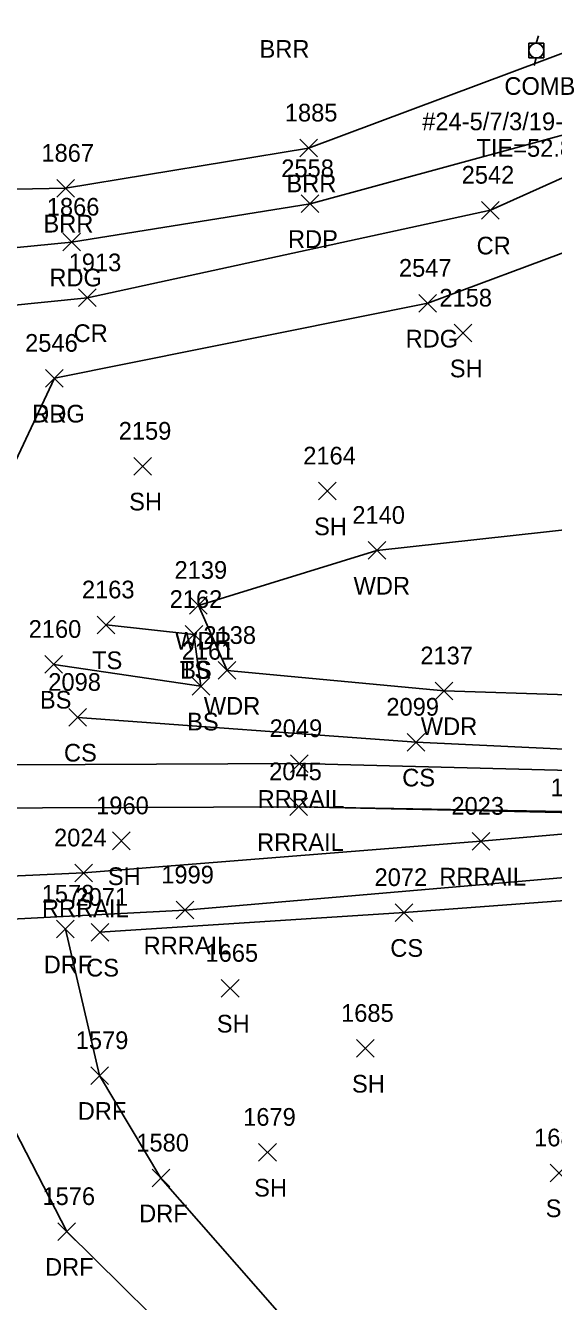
# Model space of a CAD drawing. Extents: x 1609623 to 1616187, y 756677 to 762826.
# Drawn here: x 1610243.7 to 1610303.4, y 761777.7 to 761921.9 of the extents above; entities that cross this region are included whole.
import ezdxf

# ---------------------------------------------------------------- set-up
doc = ezdxf.new("R2010")
doc.units = 0
for name, color, linetype in [('L_A', 7, 'Continuous'), ('L_I', 7, 'Continuous'), ('L_TIC', 7, 'Continuous'), ('LABL', 7, 'Continuous'), ('LAWA', 7, 'Continuous'), ('LELB', 7, 'Continuous'), ('P_A', 7, 'Continuous'), ('P_I', 7, 'Continuous'), ('P_TIC', 7, 'Continuous'), ('PET', 7, 'Continuous'), ('PEU', 7, 'Continuous'), ('PRC', 7, 'Continuous'), ('R_A', 7, 'Continuous'), ('R_I', 7, 'Continuous'), ('R_TIC', 7, 'Continuous'), ('RDF', 7, 'Continuous'), ('RDG', 7, 'Continuous'), ('RR', 7, 'Continuous'), ('U_A', 7, 'Continuous'), ('U_C', 7, 'Continuous'), ('UP', 7, 'Continuous')]:
    doc.layers.add(name, color=color, linetype=linetype)

msp = doc.modelspace()

# ---------------------------------------------------------------- linework, layer by layer
at = {"layer": 'L_TIC'}
for points in [[(1610274.72, 761907.1), (1610276.72, 761909.1)], [(1610276.72, 761907.1), (1610274.72, 761909.1)], [(1610247.25, 761902.55), (1610249.25, 761904.55)], [(1610249.25, 761902.55), (1610247.25, 761904.55)], [(1610292.19, 761886.18), (1610294.19, 761888.18)], [(1610294.19, 761886.18), (1610292.19, 761888.18)], [(1610255.95, 761871.13), (1610257.95, 761873.13)], [(1610257.95, 761871.13), (1610255.95, 761873.13)], [(1610276.85, 761868.33), (1610278.85, 761870.33)], [(1610278.85, 761868.33), (1610276.85, 761870.33)], [(1610282.44, 761861.62), (1610284.44, 761863.62)], [(1610284.44, 761861.62), (1610282.44, 761863.62)], [(1610262.26, 761855.4), (1610264.26, 761857.4)], [(1610264.26, 761855.4), (1610262.26, 761857.4)], [(1610251.83, 761853.19), (1610253.83, 761855.19)], [(1610253.83, 761853.19), (1610251.83, 761855.19)], [(1610261.75, 761852.11), (1610263.75, 761854.11)], [(1610263.75, 761852.11), (1610261.75, 761854.11)], [(1610261.75, 761852.11), (1610263.75, 761854.11)], [(1610263.75, 761852.11), (1610261.75, 761854.11)], [(1610245.9, 761848.73), (1610247.9, 761850.73)], [(1610247.9, 761848.73), (1610245.9, 761850.73)], [(1610265.51, 761848.04), (1610267.51, 761850.04)], [(1610267.51, 761848.04), (1610265.51, 761850.04)], [(1610262.54, 761846.26), (1610264.54, 761848.26)], [(1610264.54, 761846.26), (1610262.54, 761848.26)], [(1610290.04, 761845.73), (1610292.04, 761847.73)], [(1610292.04, 761845.73), (1610290.04, 761847.73)], [(1610248.62, 761842.74), (1610250.62, 761844.74)], [(1610250.62, 761842.74), (1610248.62, 761844.74)], [(1610286.86, 761839.93), (1610288.86, 761841.93)], [(1610288.86, 761839.93), (1610286.86, 761841.93)], [(1610253.53, 761828.78), (1610255.53, 761830.78)], [(1610255.53, 761828.78), (1610253.53, 761830.78)], [(1610285.51, 761820.67), (1610287.51, 761822.67)], [(1610287.51, 761820.67), (1610285.51, 761822.67)], [(1610251.13, 761818.44), (1610253.13, 761820.44)], [(1610253.13, 761818.44), (1610251.13, 761820.44)], [(1610265.85, 761812.11), (1610267.85, 761814.11)], [(1610267.85, 761812.11), (1610265.85, 761814.11)], [(1610281.13, 761805.32), (1610283.13, 761807.32)], [(1610283.13, 761805.32), (1610281.13, 761807.32)], [(1610270.07, 761793.57), (1610272.07, 761795.57)], [(1610272.07, 761793.57), (1610270.07, 761795.57)], [(1610303.03, 761791.24), (1610305.03, 761793.24)], [(1610305.03, 761791.24), (1610303.03, 761793.24)]]:
    msp.add_lwpolyline(points, dxfattribs=at)
at = {"layer": 'LABL'}
for points in [[(1610248.25, 761903.55), (1610212.86, 761902.85), (1610172.33, 761900.95), (1610131.44, 761903.3), (1610100.93, 761896.76), (1610074.3, 761892.77), (1610070.02, 761901.24), (1610088.05, 761924.14), (1610103.11, 761932.23), (1610130.22, 761924.96), (1610177.67, 761924.02), (1610222.12, 761925.25), (1610272.69, 761923.3), (1610298.02, 761931.54), (1610307.47, 761946.97), (1610343.23, 761952.19), (1610333.93, 761931.55), (1610306.47, 761919.59), (1610275.72, 761908.1)], [(1610275.72, 761908.1), (1610248.25, 761903.55)]]:
    msp.add_lwpolyline(points, dxfattribs=at)
at = {"layer": 'LAWA'}
msp.add_lwpolyline([(1610526.97, 761857.61), (1610496.05, 761855.92), (1610466.25, 761855.65), (1610453.5, 761854.66), (1610420.91, 761848.73), (1610387.01, 761845.92), (1610353.13, 761844.36), (1610319.01, 761845.83), (1610291.04, 761846.73), (1610266.51, 761849.04), (1610263.26, 761856.4), (1610283.44, 761862.62), (1610306.38, 761865.12), (1610332.85, 761874.22), (1610329.32, 761884.2), (1610350.34, 761886.85), (1610367.24, 761893.33), (1610366.39, 761903.57), (1610364.69, 761910.04), (1610391.22, 761924.07)], dxfattribs=at)
at = {"layer": 'LELB'}
for points in [[(1610249.62, 761843.74), (1610287.86, 761840.93), (1610324.56, 761839.21), (1610370.55, 761840.35), (1610409.04, 761843.86), (1610454.55, 761848.66), (1610503.04, 761852.15), (1610552.78, 761856.55), (1610588.39, 761859.94), (1610611.21, 761862.91), (1610623.76, 761863.72)], [(1610262.75, 761853.11), (1610252.83, 761854.19)], [(1610246.9, 761849.73), (1610263.54, 761847.26), (1610262.75, 761853.11)], [(1610252.13, 761819.44), (1610286.51, 761821.67), (1610318.33, 761824.07)]]:
    msp.add_lwpolyline(points, dxfattribs=at)
at = {"layer": 'P_TIC'}
for points in [[(1610274.89, 761900.81), (1610276.89, 761902.81)], [(1610276.89, 761900.81), (1610274.89, 761902.81)], [(1610295.28, 761900.07), (1610297.28, 761902.07)], [(1610297.28, 761900.07), (1610295.28, 761902.07)], [(1610247.92, 761896.46), (1610249.92, 761898.46)], [(1610249.92, 761896.46), (1610247.92, 761898.46)], [(1610249.72, 761890.17), (1610251.72, 761892.17)], [(1610251.72, 761890.17), (1610249.72, 761892.17)], [(1610288.19, 761889.55), (1610290.19, 761891.55)], [(1610290.19, 761889.55), (1610288.19, 761891.55)], [(1610245.98, 761881.07), (1610247.98, 761883.07)], [(1610247.98, 761881.07), (1610245.98, 761883.07)]]:
    msp.add_lwpolyline(points, dxfattribs=at)
at = {"layer": 'PET'}
for points in [[(1610414.5, 761964.62), (1610377.71, 761946.31), (1610343.21, 761928.18), (1610307.99, 761910.55), (1610275.89, 761901.81)], [(1610275.89, 761901.81), (1610248.92, 761897.46)]]:
    msp.add_lwpolyline(points, dxfattribs=at)
at = {"layer": 'PEU'}
for points in [[(1610246.98, 761882.07), (1610289.19, 761890.55), (1610323.19, 761903.21)], [(1610061.53, 761886.05), (1610095.83, 761889.43), (1610133.36, 761892.01), (1610173.59, 761893.05), (1610213.17, 761893.96), (1610248.92, 761897.46)]]:
    msp.add_lwpolyline(points, dxfattribs=at)
at = {"layer": 'PRC'}
for points in [[(1610478.04, 761990.3), (1610447.54, 761976.31), (1610423.7, 761963.3), (1610382.39, 761941.65), (1610345.03, 761922.97), (1610296.28, 761901.07)], [(1610296.28, 761901.07), (1610250.72, 761891.17)], [(1610012.87, 761874.99), (1610052.18, 761877.05), (1610092.88, 761880.29), (1610131.85, 761882.19), (1610172.93, 761884.85), (1610214.04, 761887.46), (1610250.72, 761891.17)]]:
    msp.add_lwpolyline(points, dxfattribs=at)
at = {"layer": 'R_TIC'}
for points in [[(1610245.98, 761881.07), (1610247.98, 761883.07)], [(1610247.98, 761881.07), (1610245.98, 761883.07)], [(1610273.66, 761837.51), (1610275.66, 761839.51)], [(1610275.66, 761837.51), (1610273.66, 761839.51)], [(1610273.6, 761832.63), (1610275.6, 761834.63)], [(1610275.6, 761832.63), (1610273.6, 761834.63)], [(1610273.6, 761832.63), (1610275.6, 761834.63)], [(1610275.6, 761832.63), (1610273.6, 761834.63)], [(1610294.2, 761828.73), (1610296.2, 761830.73)], [(1610296.2, 761828.73), (1610294.2, 761830.73)], [(1610249.28, 761825.15), (1610251.28, 761827.15)], [(1610251.28, 761825.15), (1610249.28, 761827.15)], [(1610260.76, 761820.96), (1610262.76, 761822.96)], [(1610262.76, 761820.96), (1610260.76, 761822.96)], [(1610247.23, 761818.8), (1610249.23, 761820.8)], [(1610249.23, 761818.8), (1610247.23, 761820.8)], [(1610251.09, 761802.24), (1610253.09, 761804.24)], [(1610253.09, 761802.24), (1610251.09, 761804.24)], [(1610258.02, 761790.66), (1610260.02, 761792.66)], [(1610260.02, 761790.66), (1610258.02, 761792.66)], [(1610247.38, 761784.61), (1610249.38, 761786.61)], [(1610249.38, 761784.61), (1610247.38, 761786.61)]]:
    msp.add_lwpolyline(points, dxfattribs=at)
at = {"layer": 'RDF'}
for points in [[(1610248.23, 761819.8), (1610252.09, 761803.24), (1610259.02, 761791.66), (1610278.62, 761769.29), (1610292.65, 761756.84)], [(1610264.31, 761756.11), (1610264.09, 761770.09), (1610248.38, 761785.61), (1610231.28, 761818.76)]]:
    msp.add_lwpolyline(points, dxfattribs=at)
at = {"layer": 'RDG'}
msp.add_lwpolyline([(1610239.97, 761839.19), (1610239.25, 761851.99), (1610240.2, 761867.74), (1610246.98, 761882.07)], dxfattribs=at)
at = {"layer": 'RR'}
for points in [[(1610920.34, 761877.5), (1610875.2, 761880.63), (1610823.88, 761880.35), (1610770.14, 761877.16), (1610718.25, 761872.56), (1610624.39, 761862.75), (1610528.95, 761852.85), (1610433.45, 761843.38), (1610390.08, 761839.1), (1610343.15, 761834.31), (1610326.86, 761832.49), (1610295.2, 761829.73), (1610250.28, 761826.15), (1610201.81, 761823.95), (1610155.3, 761823.62), (1610106.26, 761824.63), (1610057.65, 761827.02), (1610007.52, 761831.91), (1609961.32, 761837.48), (1609915.47, 761844.69), (1609871.57, 761853.1), (1609828.18, 761862.73), (1609811.27, 761866.9)], [(1610356.77, 761837.2), (1610311.16, 761837.59), (1610274.66, 761838.51), (1610226.22, 761838.28), (1610178.94, 761837.67), (1610131.97, 761838.32), (1610083.45, 761840.67), (1610036.86, 761844.06), (1609989.49, 761848.51), (1609944.78, 761853.81), (1609900.87, 761860.46), (1609856.95, 761868.77), (1609813.49, 761878.61)], [(1609812.23, 761861.59), (1609849.51, 761852.68), (1609889.11, 761844.53), (1609934.67, 761836.61), (1609980.82, 761829.97), (1610026.24, 761824.91), (1610071.82, 761821.22), (1610118.39, 761819.39), (1610165.38, 761818.61), (1610213.1, 761819.4), (1610261.76, 761821.96), (1610309.94, 761826.07), (1610356.6, 761830.72), (1610389.15, 761834), (1610434.7, 761838.51), (1610480.7, 761843.13), (1610575.97, 761852.51), (1610672.94, 761862.83), (1610719.08, 761867.65), (1610767.25, 761871.97), (1610815.87, 761875.05), (1610864.69, 761875.82), (1610894.81, 761874.78)], [(1609812.59, 761873.79), (1609856.08, 761863.93), (1609900.7, 761855.53), (1609944.64, 761848.95), (1609989.39, 761843.6), (1610036.39, 761839.13), (1610083.14, 761835.83), (1610131.98, 761833.39), (1610178.86, 761832.74), (1610226.26, 761833.42), (1610274.6, 761833.63)], [(1610326.86, 761832.49), (1610274.6, 761833.63), (1610353.99, 761832.22)]]:
    msp.add_lwpolyline(points, dxfattribs=at)
at = {"layer": 'UP'}
for p, q in [((1610301.71, 761920.78), (1610301.46, 761919.94)), ((1610300.63, 761918.28), (1610300.63, 761919.94)), ((1610300.63, 761919.94), (1610302.3, 761919.94)), ((1610301.46, 761919.11), (1610301.46, 761919.11)), ((1610302.3, 761919.94), (1610302.3, 761918.28)), ((1610302.3, 761918.28), (1610300.63, 761918.28)), ((1610301.21, 761917.44), (1610301.46, 761918.28))]:
    msp.add_line(p, q, dxfattribs=at)
msp.add_circle((1610301.46, 761919.11), 0.833, dxfattribs=at)

# ---------------------------------------------------------------- texts
at = {"layer": 'L_A'}
for s, p in [('BRR', (1610270.17, 761918.3)), ('BRR', (1610273.21, 761903.1)), ('BRR', (1610245.74, 761898.55)), ('SH', (1610291.68, 761882.18)), ('SH', (1610255.43, 761867.13)), ('SH', (1610276.34, 761864.33)), ('WDR', (1610280.8, 761857.62)), ('WDR', (1610260.62, 761851.4)), ('TS', (1610251.24, 761849.19)), ('TS', (1610261.16, 761848.11)), ('BS', (1610261.2, 761848.11)), ('BS', (1610245.34, 761844.73)), ('WDR', (1610263.87, 761844.04)), ('BS', (1610261.98, 761842.26)), ('WDR', (1610288.4, 761841.73)), ('CS', (1610248.06, 761838.74)), ('CS', (1610286.3, 761835.93)), ('SH', (1610253.02, 761824.78)), ('CS', (1610284.95, 761816.67)), ('CS', (1610250.57, 761814.44)), ('SH', (1610265.34, 761808.11)), ('SH', (1610280.62, 761801.32)), ('SH', (1610269.56, 761789.57)), ('SH', (1610302.52, 761787.24))]:
    msp.add_text(s, height=2, dxfattribs=at).set_placement(p)
at = {"layer": 'L_I'}
for s, p in [('1885', (1610273.03, 761911.1)), ('1867', (1610245.51, 761906.55)), ('2158', (1610290.5, 761890.18)), ('2159', (1610254.25, 761875.13)), ('2164', (1610275.11, 761872.33)), ('2140', (1610280.66, 761865.62)), ('2139', (1610260.56, 761859.4)), ('2163', (1610250.09, 761857.19)), ('2162', (1610260.01, 761856.11)), ('2162', (1610260.01, 761856.11)), ('2160', (1610244.07, 761852.73)), ('2138', (1610263.82, 761852.04)), ('2161', (1610261.37, 761850.26)), ('2137', (1610288.35, 761849.73)), ('2098', (1610246.29, 761846.74)), ('2099', (1610284.51, 761843.93)), ('1959', (1610303.08, 761834.82)), ('1960', (1610251.7, 761832.78)), ('2072', (1610283.17, 761824.67)), ('2071', (1610249.36, 761822.44)), ('1665', (1610264.06, 761816.11)), ('1685', (1610279.39, 761809.32)), ('1679', (1610268.32, 761797.57)), ('1680', (1610301.21, 761795.24))]:
    msp.add_text(s, height=2, dxfattribs=at).set_placement(p)
at = {"layer": 'P_A'}
for s, p in [('RDP', (1610273.38, 761896.81)), ('CR', (1610294.71, 761896.07)), ('RDG', (1610246.41, 761892.46)), ('CR', (1610249.15, 761886.17)), ('RDG', (1610286.68, 761885.55)), ('RDG', (1610244.47, 761877.07))]:
    msp.add_text(s, height=2, dxfattribs=at).set_placement(p)
at = {"layer": 'P_I'}
for s, p in [('2558', (1610272.63, 761904.81)), ('2542', (1610293.02, 761904.07)), ('1866', (1610246.12, 761900.46)), ('1913', (1610248.59, 761894.17)), ('2547', (1610285.93, 761893.55)), ('2546', (1610243.67, 761885.07))]:
    msp.add_text(s, height=2, dxfattribs=at).set_placement(p)
at = {"layer": 'R_A'}
for s, p in [('DRG', (1610244.47, 761877.07)), ('RRRAIL', (1610269.95, 761833.51)), ('RRRAIL', (1610269.89, 761828.63)), ('RRRAIL', (1610269.89, 761828.63)), ('RRRAIL', (1610290.49, 761824.73)), ('RRRAIL', (1610245.57, 761821.15)), ('RRRAIL', (1610257.06, 761816.96)), ('DRF', (1610245.77, 761814.8)), ('DRF', (1610249.62, 761798.24)), ('DRF', (1610256.56, 761786.66)), ('DRF', (1610245.92, 761780.61))]:
    msp.add_text(s, height=2, dxfattribs=at).set_placement(p)
at = {"layer": 'R_I'}
for s, p in [('2546', (1610243.67, 761885.07)), ('2049', (1610271.31, 761841.51)), ('2045', (1610271.26, 761836.63)), ('2045', (1610271.26, 761836.63)), ('2023', (1610291.86, 761832.73)), ('2024', (1610246.94, 761829.15)), ('1999', (1610259.06, 761824.96)), ('1578', (1610245.54, 761822.8)), ('1579', (1610249.39, 761806.24)), ('1580', (1610256.24, 761794.66)), ('1576', (1610245.63, 761788.61))]:
    msp.add_text(s, height=2, dxfattribs=at).set_placement(p)
at = {"layer": 'U_A'}
msp.add_text('COMB', height=2, dxfattribs=at).set_placement((1610297.85, 761914.11))
at = {"layer": 'U_C'}
for s, p in [('#24-5/7/3/19-2-1', (1610288.57, 761910.11)), ('TIE=52.85', (1610294.69, 761907.11))]:
    msp.add_text(s, height=2, dxfattribs=at).set_placement(p)

doc.saveas('drawing.dxf')
